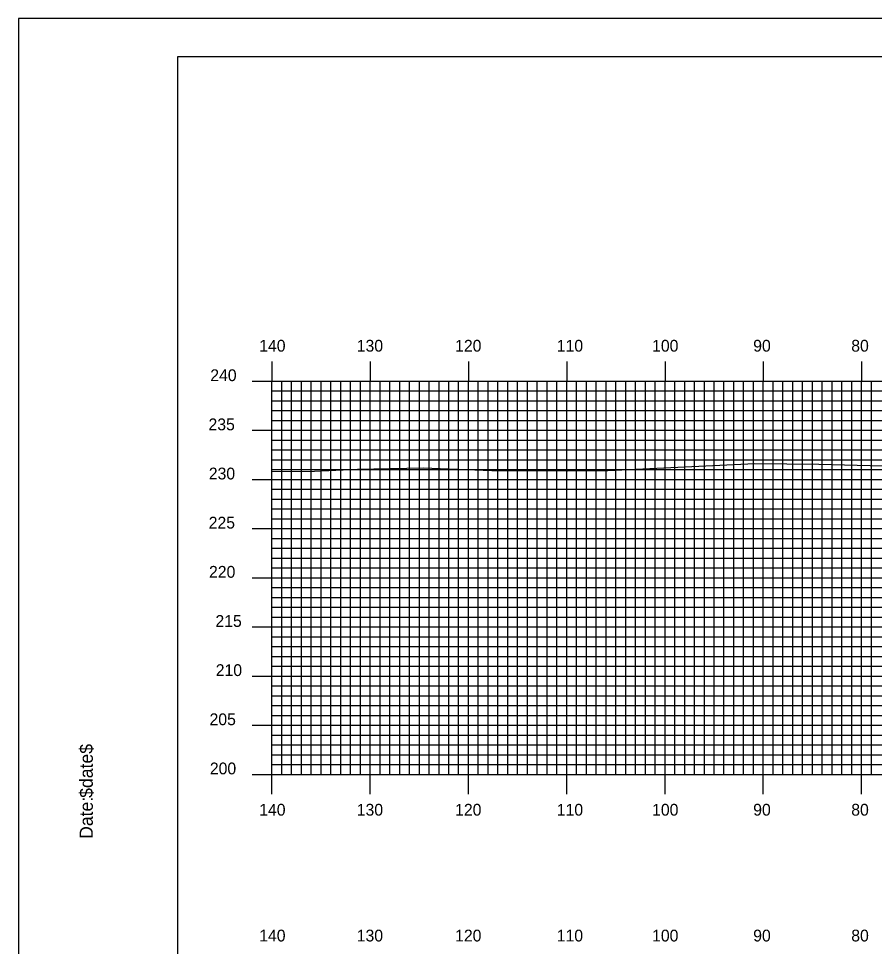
# Model space of a CAD drawing. Extents: x 1801536 to 1801879, y 442591 to 442811.
# Drawn here: x 1801535.8 to 1801622.9, y 442716.2 to 442810.5 of the extents above; entities that cross this region are included whole.
import ezdxf

# ---------------------------------------------------------------- set-up
doc = ezdxf.new("R2010")
doc.units = 0
for name, color, linetype in [('BORDER', 7, 'Continuous'), ('H_V ANNOTATION', 7, 'Continuous'), ('MAJOR', 7, 'Continuous'), ('MINOR', 7, 'Continuous'), ('PLOT BOUNDARY', 7, 'Continuous'), ('S_Roadway_Centerline', 7, 'Continuous')]:
    doc.layers.add(name, color=color, linetype=linetype)

msp = doc.modelspace()

# ---------------------------------------------------------------- linework, layer by layer
at = {"layer": 'BORDER'}
msp.add_lwpolyline([(1801551.975, 442596.665), (1801871.975, 442596.665), (1801871.975, 442806.665), (1801551.975, 442806.665)], close=True, dxfattribs=at)
at = {"layer": 'MAJOR'}
for p, q in [((1801561.575, 442775.669), (1801561.575, 442773.665)), ((1801571.575, 442775.669), (1801571.575, 442773.665)), ((1801581.575, 442775.669), (1801581.575, 442773.665)), ((1801591.575, 442775.669), (1801591.575, 442773.665)), ((1801601.575, 442775.669), (1801601.575, 442773.665)), ((1801611.575, 442775.669), (1801611.575, 442773.665)), ((1801621.575, 442775.669), (1801621.575, 442773.665)), ((1801559.571, 442773.665), (1801561.575, 442773.665)), ((1801561.575, 442773.665), (1801841.575, 442773.665)), ((1801561.575, 442733.665), (1801561.575, 442773.665)), ((1801561.575, 442733.665), (1801561.575, 442773.665)), ((1801561.575, 442773.665), (1801841.575, 442773.665)), ((1801571.575, 442733.665), (1801571.575, 442773.665)), ((1801581.575, 442733.665), (1801581.575, 442773.665)), ((1801591.575, 442733.665), (1801591.575, 442773.665)), ((1801601.575, 442733.665), (1801601.575, 442773.665)), ((1801611.575, 442733.665), (1801611.575, 442773.665)), ((1801621.575, 442733.665), (1801621.575, 442773.665)), ((1801559.571, 442768.665), (1801561.575, 442768.665)), ((1801561.575, 442768.665), (1801841.575, 442768.665)), ((1801559.571, 442763.665), (1801561.575, 442763.665)), ((1801561.575, 442763.665), (1801841.575, 442763.665)), ((1801559.571, 442758.665), (1801561.575, 442758.665)), ((1801561.575, 442758.665), (1801841.575, 442758.665)), ((1801559.571, 442753.665), (1801561.575, 442753.665)), ((1801561.575, 442753.665), (1801841.575, 442753.665)), ((1801559.571, 442748.665), (1801561.575, 442748.665)), ((1801561.575, 442748.665), (1801841.575, 442748.665)), ((1801559.571, 442743.665), (1801561.575, 442743.665)), ((1801561.575, 442743.665), (1801841.575, 442743.665)), ((1801559.571, 442738.665), (1801561.575, 442738.665)), ((1801561.575, 442738.665), (1801841.575, 442738.665)), ((1801559.571, 442733.665), (1801561.575, 442733.665)), ((1801561.575, 442733.665), (1801841.575, 442733.665)), ((1801561.575, 442733.665), (1801841.575, 442733.665)), ((1801561.575, 442731.661), (1801561.575, 442733.665)), ((1801571.575, 442731.661), (1801571.575, 442733.665)), ((1801581.575, 442731.661), (1801581.575, 442733.665)), ((1801591.575, 442731.661), (1801591.575, 442733.665)), ((1801601.575, 442731.661), (1801601.575, 442733.665)), ((1801611.575, 442731.661), (1801611.575, 442733.665)), ((1801621.575, 442731.661), (1801621.575, 442733.665))]:
    msp.add_line(p, q, dxfattribs=at)
at = {"layer": 'MINOR'}
for p, q in [((1801562.575, 442733.665), (1801562.575, 442773.665)), ((1801563.575, 442733.665), (1801563.575, 442773.665)), ((1801564.575, 442733.665), (1801564.575, 442773.665)), ((1801565.575, 442733.665), (1801565.575, 442773.665)), ((1801566.575, 442733.665), (1801566.575, 442773.665)), ((1801567.575, 442733.665), (1801567.575, 442773.665)), ((1801568.575, 442733.665), (1801568.575, 442773.665)), ((1801569.575, 442733.665), (1801569.575, 442773.665)), ((1801570.575, 442733.665), (1801570.575, 442773.665)), ((1801572.575, 442733.665), (1801572.575, 442773.665)), ((1801573.575, 442733.665), (1801573.575, 442773.665)), ((1801574.575, 442733.665), (1801574.575, 442773.665)), ((1801575.575, 442733.665), (1801575.575, 442773.665)), ((1801576.575, 442733.665), (1801576.575, 442773.665)), ((1801577.575, 442733.665), (1801577.575, 442773.665)), ((1801578.575, 442733.665), (1801578.575, 442773.665)), ((1801579.575, 442733.665), (1801579.575, 442773.665)), ((1801580.575, 442733.665), (1801580.575, 442773.665)), ((1801582.575, 442733.665), (1801582.575, 442773.665)), ((1801583.575, 442733.665), (1801583.575, 442773.665)), ((1801584.575, 442733.665), (1801584.575, 442773.665)), ((1801585.575, 442733.665), (1801585.575, 442773.665)), ((1801586.575, 442733.665), (1801586.575, 442773.665)), ((1801587.575, 442733.665), (1801587.575, 442773.665)), ((1801588.575, 442733.665), (1801588.575, 442773.665)), ((1801589.575, 442733.665), (1801589.575, 442773.665)), ((1801590.575, 442733.665), (1801590.575, 442773.665)), ((1801592.575, 442733.665), (1801592.575, 442773.665)), ((1801593.575, 442733.665), (1801593.575, 442773.665)), ((1801594.575, 442733.665), (1801594.575, 442773.665)), ((1801595.575, 442733.665), (1801595.575, 442773.665)), ((1801596.575, 442733.665), (1801596.575, 442773.665)), ((1801597.575, 442733.665), (1801597.575, 442773.665)), ((1801598.575, 442733.665), (1801598.575, 442773.665)), ((1801599.575, 442733.665), (1801599.575, 442773.665)), ((1801600.575, 442733.665), (1801600.575, 442773.665)), ((1801602.575, 442733.665), (1801602.575, 442773.665)), ((1801603.575, 442733.665), (1801603.575, 442773.665)), ((1801604.575, 442733.665), (1801604.575, 442773.665)), ((1801605.575, 442733.665), (1801605.575, 442773.665)), ((1801606.575, 442733.665), (1801606.575, 442773.665)), ((1801607.575, 442733.665), (1801607.575, 442773.665)), ((1801608.575, 442733.665), (1801608.575, 442773.665)), ((1801609.575, 442733.665), (1801609.575, 442773.665)), ((1801610.575, 442733.665), (1801610.575, 442773.665)), ((1801612.575, 442733.665), (1801612.575, 442773.665)), ((1801613.575, 442733.665), (1801613.575, 442773.665)), ((1801614.575, 442733.665), (1801614.575, 442773.665)), ((1801615.575, 442733.665), (1801615.575, 442773.665)), ((1801616.575, 442733.665), (1801616.575, 442773.665)), ((1801617.575, 442733.665), (1801617.575, 442773.665)), ((1801618.575, 442733.665), (1801618.575, 442773.665)), ((1801619.575, 442733.665), (1801619.575, 442773.665)), ((1801620.575, 442733.665), (1801620.575, 442773.665)), ((1801622.575, 442733.665), (1801622.575, 442773.665)), ((1801561.575, 442772.665), (1801841.575, 442772.665)), ((1801561.575, 442772.665), (1801563.579, 442772.665)), ((1801561.575, 442771.665), (1801841.575, 442771.665)), ((1801561.575, 442771.665), (1801563.579, 442771.665)), ((1801561.575, 442770.665), (1801841.575, 442770.665)), ((1801561.575, 442770.665), (1801563.579, 442770.665)), ((1801561.575, 442769.665), (1801841.575, 442769.665)), ((1801561.575, 442769.665), (1801563.579, 442769.665)), ((1801561.575, 442767.665), (1801841.575, 442767.665)), ((1801561.575, 442767.665), (1801563.579, 442767.665)), ((1801561.575, 442766.665), (1801841.575, 442766.665)), ((1801561.575, 442766.665), (1801563.579, 442766.665)), ((1801561.575, 442765.665), (1801841.575, 442765.665)), ((1801561.575, 442765.665), (1801563.579, 442765.665)), ((1801561.575, 442764.665), (1801841.575, 442764.665)), ((1801561.575, 442764.665), (1801563.579, 442764.665)), ((1801561.575, 442762.665), (1801841.575, 442762.665)), ((1801561.575, 442762.665), (1801563.579, 442762.665)), ((1801561.575, 442761.665), (1801841.575, 442761.665)), ((1801561.575, 442761.665), (1801563.579, 442761.665)), ((1801561.575, 442760.665), (1801841.575, 442760.665)), ((1801561.575, 442760.665), (1801563.579, 442760.665)), ((1801561.575, 442759.665), (1801841.575, 442759.665)), ((1801561.575, 442759.665), (1801563.579, 442759.665)), ((1801561.575, 442757.665), (1801841.575, 442757.665)), ((1801561.575, 442757.665), (1801563.579, 442757.665)), ((1801561.575, 442756.665), (1801841.575, 442756.665)), ((1801561.575, 442756.665), (1801563.579, 442756.665)), ((1801561.575, 442755.665), (1801841.575, 442755.665)), ((1801561.575, 442755.665), (1801563.579, 442755.665)), ((1801561.575, 442754.665), (1801841.575, 442754.665)), ((1801561.575, 442754.665), (1801563.579, 442754.665)), ((1801561.575, 442752.665), (1801841.575, 442752.665)), ((1801561.575, 442752.665), (1801563.579, 442752.665)), ((1801561.575, 442751.665), (1801841.575, 442751.665)), ((1801561.575, 442751.665), (1801563.579, 442751.665)), ((1801561.575, 442750.665), (1801841.575, 442750.665)), ((1801561.575, 442750.665), (1801563.579, 442750.665)), ((1801561.575, 442749.665), (1801841.575, 442749.665)), ((1801561.575, 442749.665), (1801563.579, 442749.665)), ((1801561.575, 442747.665), (1801841.575, 442747.665)), ((1801561.575, 442747.665), (1801563.579, 442747.665)), ((1801561.575, 442746.665), (1801841.575, 442746.665)), ((1801561.575, 442746.665), (1801563.579, 442746.665)), ((1801561.575, 442745.665), (1801841.575, 442745.665)), ((1801561.575, 442745.665), (1801563.579, 442745.665)), ((1801561.575, 442744.665), (1801841.575, 442744.665)), ((1801561.575, 442744.665), (1801563.579, 442744.665)), ((1801561.575, 442742.665), (1801841.575, 442742.665)), ((1801561.575, 442742.665), (1801563.579, 442742.665)), ((1801561.575, 442741.665), (1801841.575, 442741.665)), ((1801561.575, 442741.665), (1801563.579, 442741.665)), ((1801561.575, 442740.665), (1801841.575, 442740.665)), ((1801561.575, 442740.665), (1801563.579, 442740.665)), ((1801561.575, 442739.665), (1801841.575, 442739.665)), ((1801561.575, 442739.665), (1801563.579, 442739.665)), ((1801561.575, 442737.665), (1801841.575, 442737.665)), ((1801561.575, 442737.665), (1801563.579, 442737.665)), ((1801561.575, 442736.665), (1801841.575, 442736.665)), ((1801561.575, 442736.665), (1801563.579, 442736.665)), ((1801561.575, 442735.665), (1801841.575, 442735.665)), ((1801561.575, 442735.665), (1801563.579, 442735.665)), ((1801561.575, 442734.665), (1801841.575, 442734.665)), ((1801561.575, 442734.665), (1801563.579, 442734.665))]:
    msp.add_line(p, q, dxfattribs=at)
at = {"layer": 'PLOT BOUNDARY'}
msp.add_lwpolyline([(1801535.789, 442590.547), (1801875.789, 442590.547), (1801875.789, 442810.547), (1801535.789, 442810.547)], close=True, dxfattribs=at)
at = {"layer": 'S_Roadway_Centerline'}
msp.add_lwpolyline([(1801561.575, 442764.484), (1801565.902, 442764.5), (1801570.284, 442764.695), (1801576.946, 442764.853), (1801583.94, 442764.584), (1801591.68, 442764.531), (1801595.751, 442764.579), (1801610.716, 442765.278), (1801617.226, 442765.232), (1801623.755, 442765.041)], dxfattribs=at)

# ---------------------------------------------------------------- texts
at = {"layer": 'BORDER'}
for s, p in [('$date$', (1801543.345, 442731.275)), ('Date:', (1801543.345, 442727.099))]:
    msp.add_text(s, height=1.3392, rotation=90, dxfattribs=at).set_placement(p)
at = {"layer": 'H_V ANNOTATION'}
for s, p in [('140', (1801560.28, 442776.665)), ('130', (1801570.205, 442776.665)), ('120', (1801580.216, 442776.665)), ('110', (1801590.559, 442776.665)), ('100', (1801600.259, 442776.665)), ('90', (1801610.548, 442776.665)), ('80', (1801620.526, 442776.665)), ('240', (1801555.3, 442773.665)), ('235', (1801555.118, 442768.665)), ('230', (1801555.15, 442763.665)), ('225', (1801555.139, 442758.665)), ('220', (1801555.171, 442753.665)), ('215', (1801555.824, 442748.665)), ('210', (1801555.857, 442743.665)), ('205', (1801555.225, 442738.665)), ('200', (1801555.257, 442733.665)), ('140', (1801560.28, 442729.465)), ('130', (1801570.205, 442729.465)), ('120', (1801580.216, 442729.465)), ('110', (1801590.559, 442729.465)), ('100', (1801600.259, 442729.465)), ('90', (1801610.548, 442729.465)), ('80', (1801620.526, 442729.465)), ('140', (1801560.28, 442716.665)), ('130', (1801570.205, 442716.665)), ('120', (1801580.216, 442716.665)), ('110', (1801590.559, 442716.665)), ('100', (1801600.259, 442716.665)), ('90', (1801610.548, 442716.665)), ('80', (1801620.526, 442716.665))]:
    msp.add_text(s, height=1.2, dxfattribs=at).set_placement(p)
at = {"layer": 'MAJOR'}
msp.add_text('-', height=0.012, dxfattribs=at).set_placement((1801561.567, 442733.665))

doc.saveas('drawing.dxf')
